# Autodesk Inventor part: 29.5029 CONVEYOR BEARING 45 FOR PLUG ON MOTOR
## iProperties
Created: 2007-04
Part Number: 29.5029 CONVEYOR BEARING 45 FOR PLUG ON MOTOR
Document SubType Name: Modeling
Designer: Andy Moles
Material: Aluminum-6061
Density: 2.71 g/cm^3
Author: Andy Moles
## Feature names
1. Base1
2. Hole1
3. Extrusion1
